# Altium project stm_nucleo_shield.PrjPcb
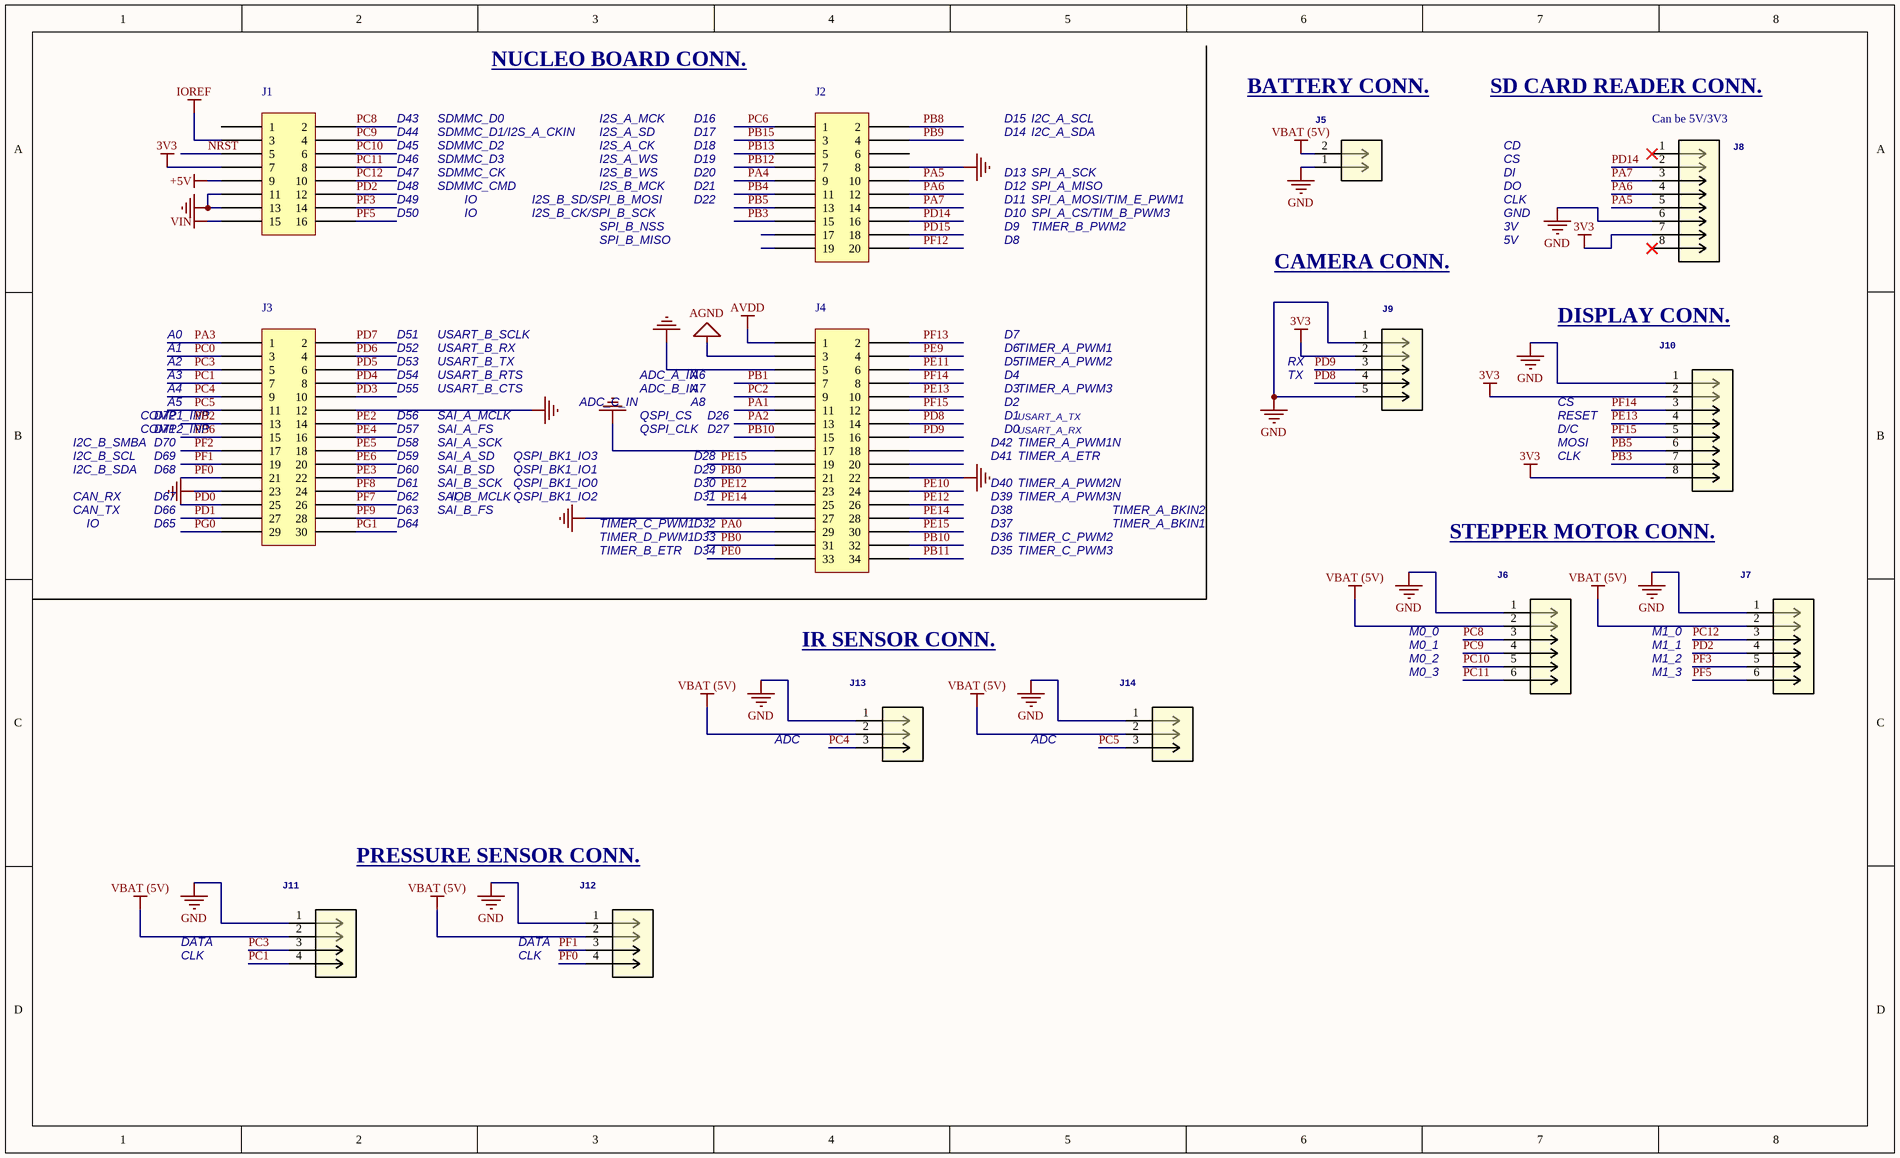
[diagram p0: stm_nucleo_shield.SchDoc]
1 sheet, 14 parts. Net scope: global (net labels, ports and power ports of the same name join across sheets).
Board file: stm_nucleo_shield.PcbDoc

## Sheet stm_nucleo_shield.SchDoc
size Legal; SheetNumber: 1; SheetTotal: 1

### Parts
J1  PPTC082LFBN-RC  [CONN-STM32-16POS]  (value not drawn)
J2  PPTC102LFBN-RC  [CONN-STM32-20POS]  (value not drawn)
J3  PPTC152LFBN-RC  [CONN-STM32-30POS]  (value not drawn)
J4  PPTC172LFBN-RC  [CONN-STM32-34POS]  (value not drawn)
J5  B2B-XH-A  [JST_B2B-XH-A]  (value not drawn)
J6  B6B-XH-A  [JST_B6B-XH-A]  (value not drawn)
J7  B6B-XH-A  [JST_B6B-XH-A]  (value not drawn)
J8  61300811121  [61300811121]  (value not drawn)
J9  B5B-XH-A  [JST_B5B-XH-A]  (value not drawn)
J10  B8B-XH-A  [JST_B8B-XH-A]  (value not drawn)
J11  B4B-XH-A  [JST_B4B-XH-A]  (value not drawn)
J12  B4B-XH-A  [JST_B4B-XH-A]  (value not drawn)
J13  B3B-XH-A  [JST_B3B-XH-A]  (value not drawn)
J14  B3B-XH-A  [JST_B3B-XH-A]  (value not drawn)

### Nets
3V3: J1.7 J8.7 J9.2 J10.2 J10.8
+5V: J1.9
AGND: J4.3
AVDD: J4.1
GND: J1.11 J1.13 J2.8 J3.12 J3.23 J4.5 J4.17 J4.22 J4.27 J5.1 J6.1 J7.1 J8.6 J9.1 J9.5 J10.1 J11.1 J12.1 J13.1 J14.1
IOREF: J1.3
VBAT (5V): J5.2 J6.2 J7.2 J11.2 J12.2 J13.2 J14.2
VIN: J1.15
NRST: J1.5
PA0: J4.29
PA1: J4.11
PA2: J4.13
PA3: J3.1
PA4: J2.9
PA5: J2.10 J8.5
PA6: J2.12 J8.4
PA7: J2.14 J8.3
PB0: J4.21 J4.31
PB1: J4.7
PB2: J3.13
PB3: J2.15 J10.7
PB4: J2.11
PB5: J2.13 J10.6
PB6: J3.15
PB8: J2.2
PB9: J2.4
PB10: J4.15 J4.32
PB11: J4.34
PB12: J2.7
PB13: J2.5
PB15: J2.3
PC0: J3.3
PC1: J3.7 J11.4
PC2: J4.9
PC3: J3.5 J11.3
PC4: J3.9 J13.3
PC5: J3.11 J14.3
PC6: J2.1
PC8: J1.2 J6.3
PC9: J1.4 J6.4
PC10: J1.6 J6.5
PC11: J1.8 J6.6
PC12: J1.10 J7.3
PD0: J3.25
PD1: J3.27
PD2: J1.12 J7.4
PD3: J3.10
PD4: J3.8
PD5: J3.6
PD6: J3.4
PD7: J3.2
PD8: J4.14 J9.4
PD9: J4.16 J9.3
PD14: J2.16 J8.2
PD15: J2.18
PE0: J4.33
PE2: J3.14
PE3: J3.22
PE4: J3.16
PE5: J3.18
PE6: J3.20
PE9: J4.4
PE10: J4.24
PE11: J4.6
PE12: J4.23 J4.26
PE13: J4.10 J10.4
PE14: J4.25 J4.28
PE15: J4.19 J4.30
PF0: J3.21 J12.4
PF1: J3.19 J12.3
PF2: J3.17
PF3: J1.14 J7.5
PF5: J1.16 J7.6
PF7: J3.26
PF8: J3.24
PF9: J3.28
PF12: J2.20
PF13: J4.2
PF14: J4.8 J10.3
PF15: J4.12 J10.5
PG0: J3.29
PG1: J3.30

Not connected (* = marked no-connect by the designer): J1 1; J2 6 17 19; J4 18 20; J8 1* 8*

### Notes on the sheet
- NUCLEO BOARD CONN.
- BATTERY CONN.
- SD CARD READER CONN.
- D43
- D44
- D45
- D46
- SDMMC_D0
- SDMMC_D1/I2S_A_CKIN
- SDMMC_D2
- SDMMC_D3
- I2S_A_SD
- I2S_A_CK
- I2S_A_WS
- I2S_A_MCK
- D16
- D17
- D18
- D19
- D14
- D15
- I2C_A_SCL
- I2C_A_SDA
- CD
- CS
- (near J8) Can be 5V/3V3
- D47
- D48
- D49
- D50
- SDMMC_CK
- SDMMC_CMD
- IO
- I2S_B_SD/SPI_B_MOSI
- I2S_B_CK/SPI_B_SCK
- I2S_B_WS
- I2S_B_MCK
- SPI_B_NSS
- D20
- D21
- D22
- D9
- D10
- D13
- D12
- D11
- TIMER_B_PWM2
- SPI_A_CS/TIM_B_PWM3
- SPI_A_MOSI/TIM_E_PWM1
- SPI_A_SCK
- SPI_A_MISO
- DI
- DO
- CLK
- GND
- 3V
- SPI_B_MISO
- D8
- CAMERA CONN.
- 5V
- A0
- A1
- A2
- D51
- D52
- D53
- USART_B_TX
- USART_B_RX
- USART_B_SCLK
- D5
- D6
- D7
- TIMER_A_PWM1
- TIMER_A_PWM2
- RX
- DISPLAY CONN.
- COMP1_INP
- COMP2_INP
- D72
- D71
- A3
- A4
- A5
- D54
- D55
- D56
- D57
- SAI_A_FS
- SAI_A_MCLK
- USART_B_CTS
- USART_B_RTS
- QSPI_CLK
- QSPI_CS
- ADC_A_IN
- ADC_B_IN
- ADC_C_IN
- A6
- A7
- A8
- D26
- D27
- D0
- D1
- D2
- D4
- D3
- USART_A_TX
- USART_A_RX
- TIMER_A_PWM3
- TX
- D/C
- RESET
- I2C_B_SCL
- I2C_B_SDA
- I2C_B_SMBA
- CAN_RX
- D70
- D69
- D68
- D67
- D58
- D59
- D60
- D61
- D62
- SAI_A_SD
- SAI_A_SCK
- SAI_B_SD
- SAI_B_SCK
- SAI_B_MCLK
- QSPI_BK1_IO0
- QSPI_BK1_IO2
- QSPI_BK1_IO1
- QSPI_BK1_IO3
- D28
- D29
- D30
- D31
- D39
- D40
- D41
- D42
- TIMER_A_PWM1N
- TIMER_A_PWM2N
- TIMER_A_PWM3N
- TIMER_A_ETR
- MOSI
- CAN_TX
- D66
- D65
- D63
- D64
- SAI_B_FS
- TIMER_D_PWM1
- TIMER_B_ETR
- TIMER_C_PWM1
- D32
- D33
- D34
- D35
- D36
- D37
- D38
- TIMER_C_PWM2
- TIMER_C_PWM3
- TIMER_A_BKIN1
- TIMER_A_BKIN2
- STEPPER MOTOR CONN.
- M0_0
- M1_0
- IR SENSOR CONN.
- M0_3
- M0_2
- M0_1
- M1_3
- M1_2
- M1_1
- ADC
- PRESSURE SENSOR CONN.
- DATA

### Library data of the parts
J1 = CONN-STM32-16POS: 16 Position Header Connector 0.100" (2.54mm) Through Hole Tin
J2 = CONN-STM32-20POS: 20 Position Header Connector 0.100" (2.54mm) Through Hole Tin
J3 = CONN-STM32-30POS: 30 Position Header Connector 0.100" (2.54mm) Through Hole Tin
J4 = CONN-STM32-34POS: 34 Position Header Connector 0.100" (2.54mm) Through Hole Tin
J5 = CONN-2POS-0001: GateName_1: G$1; SymbolName_1: HEADER_POS2; DeviceName: 43650-0215; DeviceSetName: HEADER_POS2_?
J6 J7 = CONN-6POS-0001: GateName_1: G$1; SymbolName_1: HEADER_POS2; DeviceName: 43650-0215; DeviceSetName: HEADER_POS2_?
J8 = CONN-8POS-0002: GateName_1: G$1; SymbolName_1: HEADER_POS2; DeviceName: 43650-0215; DeviceSetName: HEADER_POS2_?
J9 = CONN-5POS-0001: GateName_1: G$1; SymbolName_1: HEADER_POS2; DeviceName: 43650-0215; DeviceSetName: HEADER_POS2_?
J10 = CONN-8POS-0001: GateName_1: G$1; SymbolName_1: HEADER_POS2; DeviceName: 43650-0215; DeviceSetName: HEADER_POS2_?
J11 J12 = CONN-4POS-0001: GateName_1: G$1; SymbolName_1: HEADER_POS2; DeviceName: 43650-0215; DeviceSetName: HEADER_POS2_?
J13 J14 = CONN-3POS-0001: GateName_1: G$1; SymbolName_1: HEADER_POS2; DeviceName: 43650-0215; DeviceSetName: HEADER_POS2_?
